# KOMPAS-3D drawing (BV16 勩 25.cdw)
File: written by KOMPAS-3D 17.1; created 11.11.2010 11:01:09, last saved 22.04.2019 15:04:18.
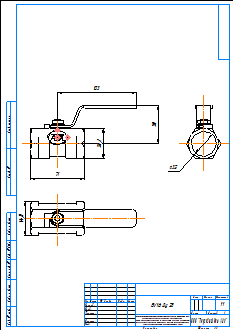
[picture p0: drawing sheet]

Sheet 1: A3, portrait

Title block, sheet 1: name: BV16 Ду 25; material: Внимание! Данный продукт является объектом авторского права ООО «Торговый Дом АДЛ». / Запрещается изменение, копирование, распространение / (в том числе путем копирования на другие сайты и ресурсы в Интернете) / или любое иное использование информации и объектов без предварительного / согласия правообладателя (ООО «Торговый Дом АДЛ»).; scale: 1:1; sheets: 1; organisation: ООО "Торговый дом АДЛ"; sheet format: A3; stored path: \\adlc.lan\data\АДЛ_ПКД\3D-модели\ADL production\Краны шаровые серии BV\BV16\KOMPAS 2D\BV16 Ду 25.cdw

Views: Спереди 1, Проекционный вид 2, Проекционный вид 3
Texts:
  user
  adl
Dimensions and other numbers on the sheet: 71; 38,2; 50; 103; 32; 44,11; 1:1; 1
